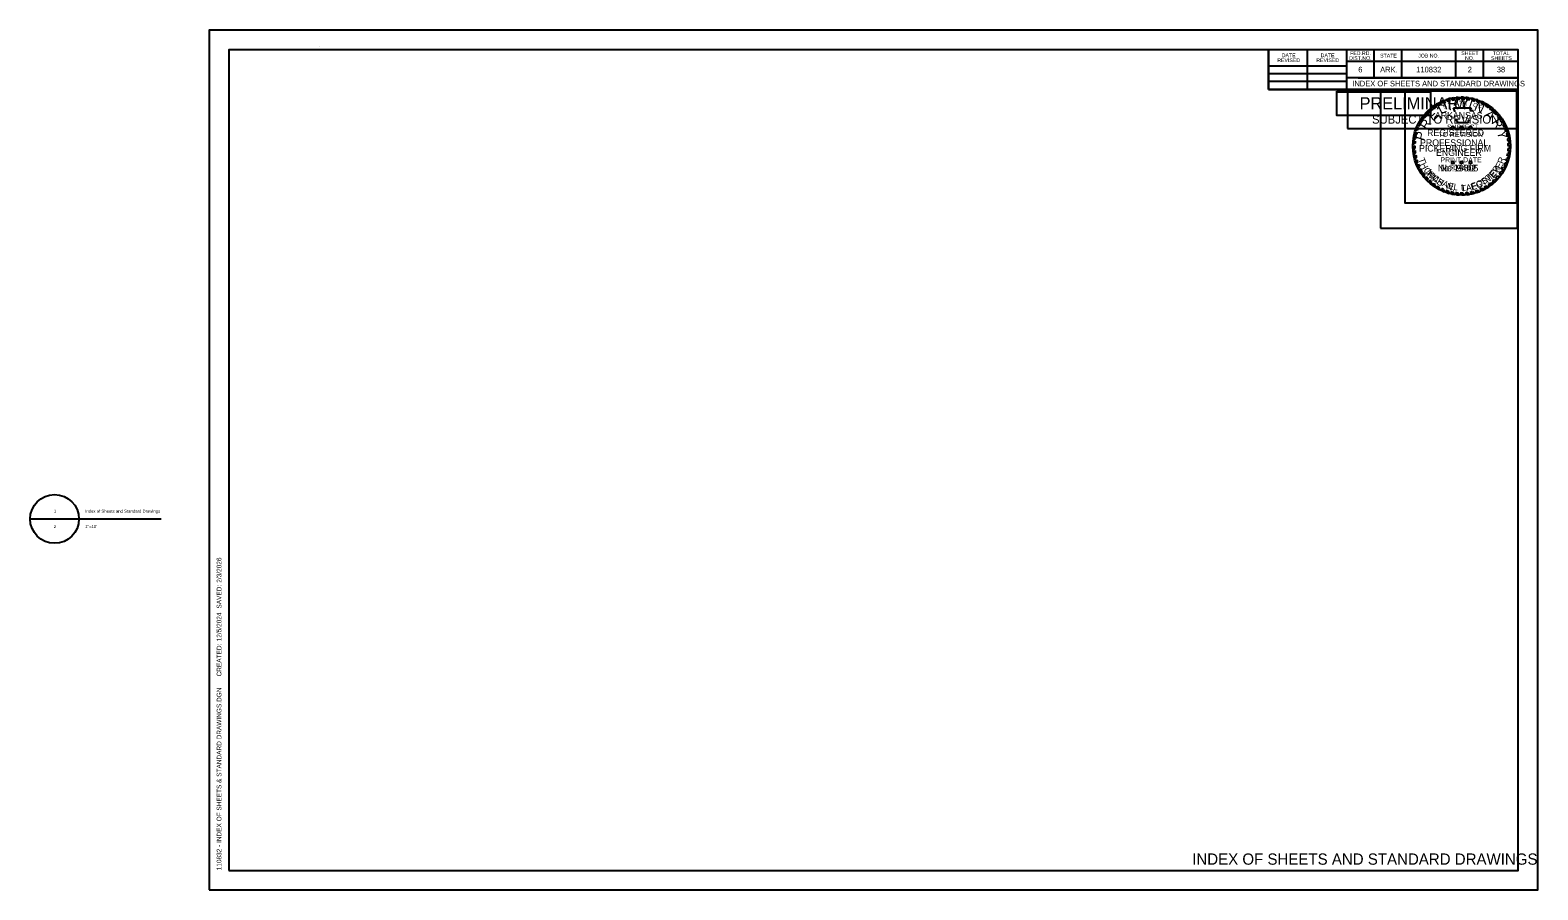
# Model space of a CAD drawing. Extents: x -0.19 to 1.42, y 0 to 0.92.
import ezdxf

# ---------------------------------------------------------------- set-up
doc = ezdxf.new("R2010")
doc.units = 0
for name, color, linetype in [('Default', 7, 'Continuous'), ('DSN_DRFT_Guideline-No-Plot', 7, 'Continuous'), ('SHET_Annotations', 7, 'Continuous'), ('SHET_Border-Lines', 7, 'Continuous'), ('SHET_Border-Text', 7, 'Continuous'), ('SHET_Stamp-Prelim', 7, 'Continuous'), ('SHET_Stamp-Seal', 7, 'Continuous'), ('STAMP_PE DIG SIG', 7, 'Continuous'), ('STAMP_PE_BACKGROUND', 7, 'Continuous'), ('STAMP_PE_FOSTER', 7, 'Continuous'), ('STAMP_PE_SEAL-INFO', 7, 'Continuous'), ('STAMP_PE_TAEGTMEYER', 7, 'Continuous'), ('STAMP_PRELIMINARY', 7, 'Continuous')]:
    doc.layers.add(name, color=color, linetype=linetype)

msp = doc.modelspace()

# ---------------------------------------------------------------- linework, layer by layer
at = {"layer": 'Default'}
for p, q in [((-0.191, 0.3955), (-0.1389, 0.3955)), ((-0.1647, 0.3955), (-0.0512, 0.3955))]:
    msp.add_line(p, q, dxfattribs=at)
msp.add_circle((-0.165, 0.3955), 0.026, dxfattribs=at)
at = {"layer": 'DSN_DRFT_Guideline-No-Plot'}
msp.add_lwpolyline([(0, 0), (1.4167, 0), (1.4167, 0.9167), (0, 0.9167)], close=True, dxfattribs=at)
at = {"layer": 'SHET_Border-Lines'}
for p, q in [((0.1176, 0.8988), (0.1176, 0.8988)), ((0.1176, 0.8988), (0.1176, 0.8988)), ((1.1296, 0.8534), (1.1296, 0.8958)), ((1.1711, 0.8534), (1.1711, 0.8958)), ((1.2127, 0.8958), (1.2127, 0.8534)), ((1.2417, 0.8958), (1.2417, 0.866)), ((1.2712, 0.8958), (1.2712, 0.866)), ((1.3289, 0.8958), (1.3289, 0.866)), ((1.3584, 0.8958), (1.3584, 0.866)), ((1.1296, 0.8786), (1.2127, 0.8786)), ((1.1296, 0.8706), (1.2127, 0.8706)), ((1.3958, 0.8832), (1.2127, 0.8832)), ((1.3958, 0.8833), (1.3958, 0.8833)), ((1.1296, 0.8622), (1.2127, 0.8622)), ((1.3958, 0.8534), (1.1296, 0.8534)), ((1.3958, 0.866), (1.2127, 0.866)), ((1.2252, 0.866), (1.3958, 0.866))]:
    msp.add_line(p, q, dxfattribs=at)
for points in [[(0.0208, 0.0208), (1.3958, 0.0208), (1.3958, 0.8958), (0.0208, 0.8958)], [(1.1296, 0.8534), (1.3958, 0.8534), (1.3958, 0.8958), (1.1296, 0.8958)]]:
    msp.add_lwpolyline(points, close=True, dxfattribs=at)
at = {"layer": 'SHET_Stamp-Prelim'}
msp.add_lwpolyline([(1.2137, 0.8119), (1.3948, 0.8119), (1.3948, 0.8524), (1.2137, 0.8524)], close=True, dxfattribs=at)
at = {"layer": 'SHET_Stamp-Seal'}
msp.add_line((1.3219, 0.7895), (1.3219, 0.7895), dxfattribs=at)
msp.add_lwpolyline([(1.249, 0.7057), (1.3948, 0.7057), (1.3948, 0.8524), (1.249, 0.8524)], close=True, dxfattribs=at)
at = {"layer": 'STAMP_PE DIG SIG'}
msp.add_lwpolyline([(1.2022, 0.8508), (1.3022, 0.8508), (1.3022, 0.8258), (1.2022, 0.8258)], close=True, dxfattribs=at)
at = {"layer": 'STAMP_PE_BACKGROUND'}
for points in [[(1.2022, 0.8517), (1.3022, 0.8517), (1.3022, 0.8258), (1.2022, 0.8258)], [(1.3942, 0.8517), (1.275, 0.8517), (1.275, 0.7325), (1.3942, 0.7325)]]:
    msp.add_lwpolyline(points, close=True, dxfattribs=at)
at = {"layer": 'STAMP_PE_SEAL-INFO'}
for p, q in [((1.3066, 0.8363), (1.309, 0.8352)), ((1.3087, 0.8377), (1.3112, 0.8365)), ((1.3112, 0.8391), (1.3138, 0.8378)), ((1.3137, 0.8403), (1.3158, 0.8387)), ((1.3165, 0.8415), (1.3181, 0.8397)), ((1.3184, 0.8422), (1.3206, 0.8405)), ((1.3217, 0.8432), (1.3233, 0.8413)), ((1.3239, 0.8438), (1.3259, 0.8418)), ((1.3266, 0.8443), (1.3283, 0.8422)), ((1.3295, 0.8447), (1.331, 0.8426)), ((1.3336, 0.8427), (1.3318, 0.8449)), ((1.3364, 0.8428), (1.3348, 0.845)), ((1.3389, 0.8426), (1.3375, 0.845)), ((1.3417, 0.8424), (1.3401, 0.8448)), ((1.3441, 0.842), (1.3427, 0.8445)), ((1.3473, 0.8413), (1.3463, 0.8439)), ((1.3495, 0.8407), (1.3486, 0.8433)), ((1.352, 0.8399), (1.3512, 0.8426)), ((1.3544, 0.839), (1.3536, 0.8418)), ((1.357, 0.8379), (1.3564, 0.8406)), ((1.3594, 0.8366), (1.359, 0.8394)), ((1.3616, 0.8353), (1.3614, 0.8381)), ((1.364, 0.8337), (1.3639, 0.8366)), ((1.2917, 0.8213), (1.2946, 0.8215)), ((1.293, 0.8232), (1.2959, 0.8232)), ((1.2946, 0.8253), (1.2977, 0.8254)), ((1.2965, 0.8276), (1.2994, 0.8274)), ((1.2983, 0.8295), (1.3014, 0.8293)), ((1.3002, 0.8313), (1.3028, 0.8306)), ((1.3021, 0.833), (1.3051, 0.8325)), ((1.3042, 0.8348), (1.3068, 0.8337)), ((1.3269, 0.8337), (1.3456, 0.8337)), ((1.3276, 0.832), (1.3269, 0.8337)), ((1.3281, 0.8303), (1.3276, 0.832)), ((1.3282, 0.8297), (1.3281, 0.8303)), ((1.3293, 0.8201), (1.3291, 0.8213)), ((1.331, 0.8201), (1.3293, 0.8201)), ((1.331, 0.8177), (1.331, 0.8201)), ((1.3429, 0.8213), (1.3424, 0.8196)), ((1.3456, 0.8337), (1.3443, 0.831)), ((1.3443, 0.831), (1.3478, 0.831)), ((1.3478, 0.831), (1.347, 0.8297)), ((1.366, 0.8322), (1.3662, 0.8349)), ((1.3685, 0.8301), (1.3687, 0.8331)), ((1.3703, 0.8285), (1.3707, 0.8313)), ((1.3723, 0.8264), (1.3727, 0.8294)), ((1.3738, 0.8247), (1.3746, 0.8273)), ((1.3756, 0.8223), (1.3764, 0.8251)), ((1.3769, 0.8206), (1.3779, 0.8232)), ((1.3786, 0.8178), (1.3796, 0.8205)), ((1.2847, 0.8048), (1.2873, 0.8059)), ((1.2853, 0.8071), (1.2879, 0.808)), ((1.2862, 0.8099), (1.2889, 0.8106)), ((1.287, 0.8121), (1.2898, 0.8129)), ((1.288, 0.8145), (1.2908, 0.8151)), ((1.2891, 0.8167), (1.2918, 0.8171)), ((1.2904, 0.8191), (1.2931, 0.8192)), ((1.3252, 0.8129), (1.3241, 0.8137)), ((1.3241, 0.8137), (1.3255, 0.8137)), ((1.3248, 0.8116), (1.3252, 0.8129)), ((1.3259, 0.8124), (1.3248, 0.8116)), ((1.3255, 0.8137), (1.3259, 0.815)), ((1.3259, 0.815), (1.3264, 0.8137)), ((1.327, 0.8116), (1.3259, 0.8124)), ((1.3264, 0.8137), (1.3277, 0.8137)), ((1.3277, 0.8137), (1.3266, 0.8129)), ((1.3266, 0.8129), (1.327, 0.8116)), ((1.3423, 0.8177), (1.331, 0.8177)), ((1.3347, 0.8129), (1.3336, 0.8137)), ((1.3336, 0.8137), (1.335, 0.8137)), ((1.3343, 0.8116), (1.3347, 0.8129)), ((1.3354, 0.8124), (1.3343, 0.8116)), ((1.335, 0.8137), (1.3354, 0.815)), ((1.3354, 0.815), (1.3358, 0.8137)), ((1.3365, 0.8116), (1.3354, 0.8124)), ((1.3358, 0.8137), (1.3372, 0.8137)), ((1.3372, 0.8137), (1.3361, 0.8129)), ((1.3361, 0.8129), (1.3365, 0.8116)), ((1.3424, 0.8196), (1.3423, 0.8177)), ((1.3442, 0.8129), (1.3431, 0.8137)), ((1.3431, 0.8137), (1.3445, 0.8137)), ((1.3438, 0.8116), (1.3442, 0.8129)), ((1.3449, 0.8124), (1.3438, 0.8116)), ((1.3445, 0.8137), (1.3449, 0.815)), ((1.3449, 0.815), (1.3453, 0.8137)), ((1.346, 0.8116), (1.3449, 0.8124)), ((1.3453, 0.8137), (1.3467, 0.8137)), ((1.3467, 0.8137), (1.3456, 0.8129)), ((1.3456, 0.8129), (1.346, 0.8116)), ((1.3797, 0.8157), (1.381, 0.8182)), ((1.381, 0.813), (1.3823, 0.8157)), ((1.3818, 0.8112), (1.3832, 0.8136)), ((1.3829, 0.8081), (1.3844, 0.8107)), ((1.3835, 0.8061), (1.3851, 0.8086)), ((1.3842, 0.8029), (1.386, 0.8054)), ((1.2857, 0.796), (1.2834, 0.7946)), ((1.2856, 0.7933), (1.2834, 0.7914)), ((1.2859, 0.7984), (1.2835, 0.7968)), ((1.2857, 0.791), (1.2835, 0.7892)), ((1.2862, 0.8008), (1.2838, 0.7996)), ((1.2858, 0.7882), (1.2838, 0.7862)), ((1.2867, 0.8034), (1.2841, 0.802)), ((1.3846, 0.8008), (1.3866, 0.8028)), ((1.3849, 0.7876), (1.3874, 0.7891)), ((1.385, 0.798), (1.387, 0.7998)), ((1.3851, 0.7956), (1.3873, 0.7973)), ((1.3852, 0.7927), (1.3875, 0.7945)), ((1.3852, 0.7905), (1.3875, 0.792)), ((1.2861, 0.7858), (1.2842, 0.7837)), ((1.2866, 0.7833), (1.2847, 0.7812)), ((1.2871, 0.7809), (1.2854, 0.7786)), ((1.2878, 0.7784), (1.2861, 0.7761)), ((1.2886, 0.7761), (1.287, 0.7738)), ((1.2895, 0.7737), (1.288, 0.7713)), ((1.3252, 0.7754), (1.3241, 0.7763)), ((1.3241, 0.7763), (1.3255, 0.7763)), ((1.3248, 0.7741), (1.3252, 0.7754)), ((1.3259, 0.7749), (1.3248, 0.7741)), ((1.3255, 0.7763), (1.3259, 0.7776)), ((1.3259, 0.7776), (1.3264, 0.7763)), ((1.327, 0.7741), (1.3259, 0.7749)), ((1.3264, 0.7763), (1.3277, 0.7763)), ((1.3277, 0.7763), (1.3266, 0.7754)), ((1.3266, 0.7754), (1.327, 0.7741)), ((1.3347, 0.7754), (1.3336, 0.7763)), ((1.3336, 0.7763), (1.335, 0.7763)), ((1.3343, 0.7741), (1.3347, 0.7754)), ((1.3354, 0.7749), (1.3343, 0.7741)), ((1.335, 0.7763), (1.3354, 0.7776)), ((1.3354, 0.7776), (1.3358, 0.7763)), ((1.3365, 0.7741), (1.3354, 0.7749)), ((1.3358, 0.7763), (1.3372, 0.7763)), ((1.3372, 0.7763), (1.3361, 0.7754)), ((1.3361, 0.7754), (1.3365, 0.7741)), ((1.3442, 0.7754), (1.3431, 0.7763)), ((1.3431, 0.7763), (1.3445, 0.7763)), ((1.3438, 0.7741), (1.3442, 0.7754)), ((1.3449, 0.7749), (1.3438, 0.7741)), ((1.3445, 0.7763), (1.3449, 0.7776)), ((1.3449, 0.7776), (1.3453, 0.7763)), ((1.346, 0.7741), (1.3449, 0.7749)), ((1.3453, 0.7763), (1.3467, 0.7763)), ((1.3467, 0.7763), (1.3456, 0.7754)), ((1.3456, 0.7754), (1.346, 0.7741)), ((1.3808, 0.7724), (1.3835, 0.7729)), ((1.382, 0.7753), (1.3847, 0.776)), ((1.3827, 0.7774), (1.3855, 0.7785)), ((1.3835, 0.7802), (1.3862, 0.7813)), ((1.3841, 0.7827), (1.3867, 0.7838)), ((1.3846, 0.7855), (1.3871, 0.7867)), ((1.2905, 0.7715), (1.2892, 0.769)), ((1.2918, 0.769), (1.2907, 0.7662)), ((1.2931, 0.7667), (1.2921, 0.7641)), ((1.2942, 0.765), (1.2936, 0.7619)), ((1.2958, 0.7628), (1.2952, 0.7598)), ((1.2975, 0.7607), (1.297, 0.7578)), ((1.2992, 0.7588), (1.2988, 0.7559)), ((1.301, 0.757), (1.3008, 0.754)), ((1.3702, 0.7573), (1.3727, 0.7566)), ((1.3716, 0.7588), (1.3743, 0.7583)), ((1.3738, 0.7612), (1.3763, 0.7608)), ((1.3755, 0.7634), (1.3783, 0.7634)), ((1.3774, 0.7662), (1.3801, 0.7661)), ((1.3783, 0.7677), (1.3811, 0.768)), ((1.3799, 0.7705), (1.3826, 0.7709)), ((1.3029, 0.7552), (1.3029, 0.7523)), ((1.3049, 0.7536), (1.305, 0.7507)), ((1.3068, 0.7522), (1.307, 0.7493)), ((1.3092, 0.7506), (1.3095, 0.7478)), ((1.3111, 0.7495), (1.3117, 0.7466)), ((1.3138, 0.7481), (1.3147, 0.7452)), ((1.3159, 0.7471), (1.3169, 0.7443)), ((1.3187, 0.7461), (1.3198, 0.7433)), ((1.321, 0.7453), (1.3222, 0.7426)), ((1.3238, 0.7445), (1.325, 0.7419)), ((1.326, 0.7441), (1.3274, 0.7415)), ((1.3288, 0.7436), (1.3302, 0.7411)), ((1.3313, 0.7433), (1.3328, 0.7409)), ((1.334, 0.7432), (1.3356, 0.7409)), ((1.3365, 0.7432), (1.3384, 0.741)), ((1.3394, 0.7433), (1.3412, 0.7412)), ((1.3419, 0.7436), (1.344, 0.7416)), ((1.3444, 0.744), (1.3465, 0.7421)), ((1.3471, 0.7446), (1.3492, 0.7427)), ((1.3497, 0.7453), (1.352, 0.7436)), ((1.3524, 0.7462), (1.3549, 0.7447)), ((1.3548, 0.7471), (1.3571, 0.7456)), ((1.3573, 0.7483), (1.36, 0.7471)), ((1.3596, 0.7494), (1.3619, 0.7481)), ((1.3619, 0.7508), (1.3644, 0.7497)), ((1.3639, 0.7521), (1.3663, 0.751)), ((1.3664, 0.754), (1.369, 0.7532)), ((1.3679, 0.7553), (1.3706, 0.7545))]:
    msp.add_line(p, q, dxfattribs=at)
for radius, start, end in [(0.0521, 123.6199, 126.5906), (0.0521, 117.6544, 120.8099), (0.0498, 115.6869, 119.1583), (0.0521, 111.3124, 114.7026), (0.0498, 110.3086, 113.1659), (0.0521, 105.2339, 109.0352), (0.0498, 104.0352, 107.3615), (0.0521, 99.7525, 102.7765), (0.0498, 98.258, 101.0329), (0.0521, 93.9381, 96.5517), (0.0498, 92.1102, 95.0367), (0.0521, 87.7298, 90.6707), (0.0498, 85.9628, 88.9097), (0.0521, 81.9732, 84.8236), (0.0498, 79.9264, 82.696), (0.0521, 75.3125, 77.9426), (0.0498, 73.5575, 76.2314), (0.0521, 69.6061, 72.3058), (0.0498, 67.6248, 70.504), (0.0521, 63.1329, 66.2704), (0.0498, 61.1558, 64.3784), (0.0521, 56.9003, 60.0942), (0.0521, 147.0072, 149.899), (0.0521, 141.6056, 144.4486), (0.0498, 145.0197, 148.2104), (0.0498, 139.301, 142.5873), (0.0521, 135.4021, 138.3031), (0.0498, 133.1331, 136.2562), (0.0521, 129.7326, 132.5376), (0.0498, 127.5297, 130.9683), (0.0498, 121.9746, 125.11), (0.0498, 54.9238, 58.2702), (0.0498, 48.3016, 52.0395), (0.0521, 50.3492, 53.7159), (0.0498, 42.2212, 45.5512), (0.0521, 44.3405, 47.3929), (0.0498, 36.135, 39.5311), (0.0521, 38.1247, 41.2316), (0.0498, 29.9032, 33.6645), (0.0521, 31.9614, 35.4294), (0.0521, 164.3068, 166.894), (0.0521, 158.4077, 161.0701), (0.0498, 162.4331, 165.0013), (0.0521, 152.864, 155.5189), (0.0498, 156.3402, 159.2319), (0.0498, 151.0315, 153.573), (0.0498, 23.7732, 27.2211), (0.0521, 25.9391, 29.0125), (0.0498, 17.6802, 21.4251), (0.0521, 19.9538, 23.3141), (0.0498, 11.5444, 15.2364), (0.0521, 13.8421, 17.4447), (0.0521, 175.7409, 178.2066), (0.0521, 181.7251, 184.1626), (0.0521, 170.0003, 172.6878), (0.0498, 179.6454, 182.2633), (0.0498, 173.73, 176.4734), (0.0498, 185.4539, 188.234), (0.0498, 167.9048, 170.9039), (0.0498, 5.7599, 9.0606), (0.0498, 353.8632, 357.1274), (0.0498, 359.7329, 3.0639), (0.0521, 7.5852, 10.8621), (0.0521, 1.7215, 4.7268), (0.0521, 355.7156, 358.9569), (0.0521, 187.4204, 190.1927), (0.0521, 193.0369, 195.9973), (0.0521, 198.8967, 201.6281), (0.0498, 191.2274, 193.9858), (0.0498, 196.9675, 199.8353), (0.0498, 202.7761, 205.4791), (0.0498, 335.6038, 339.1858), (0.0498, 341.777, 345.0925), (0.0521, 337.3837, 340.9933), (0.0498, 348.0778, 351.3435), (0.0521, 343.8925, 347.035), (0.0521, 349.8305, 353.0885), (0.0521, 204.5479, 207.4328), (0.0521, 210.8636, 213.6571), (0.0498, 208.7883, 211.7934), (0.0521, 216.6115, 219.491), (0.0498, 214.1838, 217.2747), (0.0521, 222.48, 225.3801), (0.0498, 220.3909, 223.3056), (0.0498, 226.2494, 229.2407), (0.0498, 310.7744, 314.3161), (0.0521, 312.4518, 315.6633), (0.0498, 316.6531, 320.3711), (0.0521, 318.2846, 321.8043), (0.0498, 323.5851, 327.4407), (0.0498, 329.5549, 333.2076), (0.0521, 325.4405, 328.9872), (0.0521, 331.4037, 334.9332), (0.0521, 228.3665, 231.348), (0.0498, 232.229, 234.9336), (0.0521, 234.295, 236.9452), (0.0498, 238.2223, 240.8353), (0.0521, 240.1977, 242.8613), (0.0498, 244.3204, 246.9486), (0.0521, 246.576, 249.1558), (0.0498, 250.3491, 253.1216), (0.0521, 252.5967, 255.3252), (0.0498, 256.505, 259.1192), (0.0521, 258.4433, 261.1398), (0.0498, 262.3783, 265.2012), (0.0521, 264.1978, 267.1009), (0.0498, 268.3215, 271.277), (0.0521, 270.2548, 273.3361), (0.0498, 274.6157, 277.4486), (0.0521, 276.4239, 279.4357), (0.0498, 280.3459, 283.5814), (0.0521, 282.3199, 285.3702), (0.0498, 286.6423, 289.9783), (0.0521, 288.5709, 291.9733), (0.0498, 292.8745, 296.1185), (0.0521, 294.6481, 298.2166), (0.0498, 299.0768, 302.1724), (0.0521, 300.621, 303.8703), (0.0498, 304.823, 308.5143), (0.0521, 306.3721, 310.208)]:
    msp.add_arc((1.3354, 0.793), radius, start, end, dxfattribs=at)
at = {"layer": 'STAMP_PRELIMINARY'}
msp.add_circle((1.3354, 0.793), 0.0521, dxfattribs=at)

# ---------------------------------------------------------------- texts
at = {"layer": 'Default'}
for s, height, p in [('1', 0.00328, (-0.1658, 0.4021)), ('Index of Sheets and Standard Drawings', 0.003281, (-0.1324, 0.4021)), ('2', 0.00328, (-0.1659, 0.3857)), ('1"=10\'', 0.00328, (-0.1324, 0.3857))]:
    msp.add_text(s, height=height, dxfattribs=at).set_placement(p)
at = {"layer": 'SHET_Annotations'}
for s, height, p in [('6', 0.006, (1.2252, 0.8716)), ('ARK.', 0.006, (1.2485, 0.8716)), ('110832', 0.006, (1.287, 0.8716)), ('2', 0.006, (1.3419, 0.8716)), ('38', 0.006, (1.3729, 0.8717)), ('INDEX OF SHEETS AND STANDARD DRAWINGS', 0.006, (1.2188, 0.8567)), ('INDEX OF SHEETS AND STANDARD DRAWINGS', 0.012, (1.0481, 0.0268))]:
    msp.add_text(s, height=height, dxfattribs=at).set_placement(p)
at = {"layer": 'SHET_Border-Text'}
for s, p in [('REVISED', (1.1388, 0.8826)), ('DATE', (1.1436, 0.8878)), ('REVISED', (1.1804, 0.8826)), ('DATE', (1.1851, 0.8878)), ('DIST.NO.', (1.2154, 0.8849)), ('FED.RD.', (1.2165, 0.8901)), ('STATE', (1.2485, 0.8875)), ('JOB NO.', (1.2891, 0.8875)), ('SHEET', (1.335, 0.8901)), ('NO.', (1.339, 0.8849)), ('SHEETS', (1.3668, 0.8849)), ('TOTAL', (1.3686, 0.8901))]:
    msp.add_text(s, height=0.004, dxfattribs=at).set_placement(p)
for s, p in [('2/3/2026', (0.0129, 0.3275)), ('  SAVED: ', (0.0129, 0.2961)), ('12/5/2024', (0.0129, 0.265)), ('     CREATED: ', (0.0129, 0.218)), ('110832 - INDEX OF SHEETS & STANDARD DRAWINGS.DGN', (0.0129, 0.0208))]:
    msp.add_text(s, height=0.005, rotation=90, dxfattribs=at).set_placement(p)
at = {"layer": 'SHET_Stamp-Prelim'}
for s, height, p in [('PRELIMINARY', 0.013, (1.2266, 0.8322)), ('SUBJECT TO REVISION', 0.009, (1.2398, 0.817))]:
    msp.add_text(s, height=height, dxfattribs=at).set_placement(p)
at = {"layer": 'STAMP_PE_FOSTER'}
msp.add_text('No. 9402', height=0.00698, dxfattribs=at).set_placement((1.313, 0.7661))
for s, rotation, p in [('R', 54.5031, (1.373, 0.764)), ('M', 308.339, (1.297, 0.7652)), ('I', 314.1842, (1.3014, 0.7599)), ('C', 319.8733, (1.3034, 0.7579)), ('H', 327.7235, (1.3086, 0.7538)), ('A', 335.7276, (1.3141, 0.7506)), ('O', 23.719, (1.3526, 0.7487)), ('S', 31.7234, (1.3588, 0.7517)), ('T', 39.4194, (1.3641, 0.7552)), ('E', 46.9613, (1.3689, 0.7594)), ('E', 343.5779, (1.3204, 0.748)), ('L', 350.8115, (1.3263, 0.7464)), ('L', 1.2666, (1.3349, 0.7455)), ('.', 6.8035, (1.3408, 0.7459)), ('F', 15.8691, (1.3468, 0.7469))]:
    msp.add_text(s, height=0.0067, rotation=rotation, dxfattribs=at).set_placement(p)
at = {"layer": 'STAMP_PE_SEAL-INFO'}
for s, rotation, p in [('S', 23.5541, (1.3164, 0.8327)), ('T', 16.311, (1.3216, 0.8347)), ('A', 9.0679, (1.3269, 0.8361)), ('T', 1.8248, (1.3325, 0.8369)), ('E', 355.2002, (1.3375, 0.8369)), ('O', 342.2506, (1.3472, 0.8354)), ('F', 335.0075, (1.3526, 0.8335))]:
    msp.add_text(s, height=0.00436, rotation=rotation, dxfattribs=at).set_placement(p)
for s, height, p in [('ARKANSAS', 0.00698, (1.3069, 0.8223)), ('REGISTERED', 0.00698, (1.2986, 0.8038)), ('PROFESSIONAL', 0.006983, (1.2911, 0.7932)), ('ENGINEER', 0.00698, (1.3081, 0.7826))]:
    msp.add_text(s, height=height, dxfattribs=at).set_placement(p)
at = {"layer": 'STAMP_PE_TAEGTMEYER'}
for s, rotation, p in [('T', 289.646, (1.289, 0.7791)), ('H', 296.7339, (1.291, 0.7736)), ('Y', 53.9986, (1.3733, 0.7628)), ('E', 63.0984, (1.377, 0.768)), ('R', 69.57, (1.3798, 0.7735)), ('O', 303.7708, (1.2943, 0.7674)), ('M', 314.2033, (1.298, 0.7621)), ('A', 321.0594, (1.3034, 0.7567)), ('S', 327.8239, (1.308, 0.7531)), ('G', 23.3052, (1.3522, 0.7475)), ('T', 31.466, (1.3583, 0.7503)), ('M', 39.3, (1.3633, 0.7533)), ('E', 46.8094, (1.3692, 0.7582)), ('N', 344.2727, (1.3186, 0.7474)), ('.', 350.6464, (1.3254, 0.7456)), ('T', 3.0061, (1.3347, 0.7445)), ('A', 8.9826, (1.3405, 0.7448)), ('E', 17.6836, (1.3463, 0.7457))]:
    msp.add_text(s, height=0.00698, rotation=rotation, dxfattribs=at).set_placement(p)
msp.add_text('No. 19605', height=0.00698, dxfattribs=at).set_placement((1.3101, 0.7661))
at = {"layer": 'STAMP_PRELIMINARY'}
for s, rotation, p in [('L', 25.513, (1.3131, 0.8266)), ('I', 12.5248, (1.3217, 0.8309)), ('M', 3.1074, (1.3278, 0.8326)), ('I', 342.3164, (1.3416, 0.833)), ('N', 333.9382, (1.3478, 0.8315)), ('R', 56.2292, (1.2984, 0.8095)), ('E', 42.3578, (1.3048, 0.8192)), ('A', 315.6579, (1.3591, 0.8257)), ('R', 301.3831, (1.3668, 0.8184)), ('P', 73.913, (1.2953, 0.7982)), ('Y', 283.2593, (1.3729, 0.8084))]:
    msp.add_text(s, height=0.0101, rotation=rotation, dxfattribs=at).set_placement(p)
for s, height, p in [('TO REVISION', 0.005363, (1.3105, 0.8028)), ('SUBJECT', 0.00536, (1.3198, 0.8106)), ('PICKERING FIRM', 0.006983, (1.29, 0.7872)), ('PRINT DATE', 0.00536, (1.3128, 0.7757)), ('$DATE$', 0.00536, (1.3222, 0.768))]:
    msp.add_text(s, height=height, dxfattribs=at).set_placement(p)

doc.saveas('drawing.dxf')
